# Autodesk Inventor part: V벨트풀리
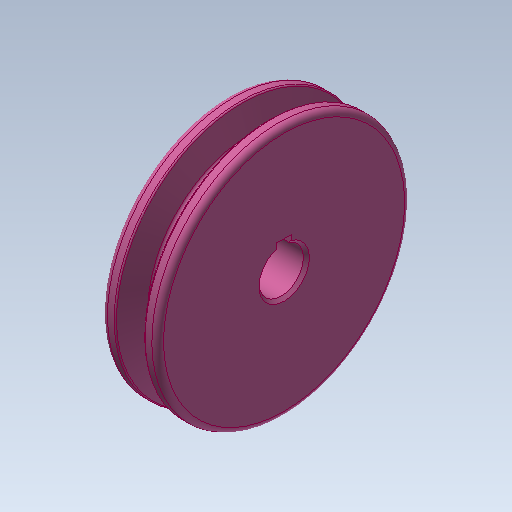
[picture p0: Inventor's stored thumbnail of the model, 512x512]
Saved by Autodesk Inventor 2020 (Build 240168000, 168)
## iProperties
Created: 2018-11
Part Number: V벨트풀리
Material: 알루미늄 6061
Document SubType Name: Modeling
Designer: mduedu
Density: 1 g/cm^3
Appearance: 분홍색
Author: mduedu
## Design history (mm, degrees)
sketch "스케치1"
  geometry: L1 (-9.5, 0)-(9.5, 0); L2 (9.5, 0)-(9.5, 42.7); L3 (9.5, 42.7)-(4.877, 42.7); L4 (-9.5, 42.7)-(-9.5, 0); L5 (-4.877, 42.7)-(-1.953, 33.7); L6 (-1.953, 33.7)-(1.953, 33.7); L7 (1.953, 33.7)-(4.877, 42.7); L8 (0, 0)-(0, 42.7); L9 (-9.5, 40)-(9.5, 40); L10 (-4.877, 42.7)-(-9.5, 42.7); L11 (4.877, 42.7)-(-4.877, 42.7); 3 further points
  constraints: 22 end point, 6 point on line, 4 parallel, 3 perpendicular, 2 midpoint, 1 coincident, 1 horizontal, 1 vertical, 1 other
  dimensions: "d2" = 19 distance of L2.end L4.start; "d3" = 80 diameter of L9 L1; "d4" = 36 deg angle of L7 L5; "d5" = 6.3 distance between parallel lines of L6 L9; "d6" = 8 distance of point (4, 40) point (-4, 40); "d27" = 2.7 distance between parallel lines of L3 L9
revolve "회전1" sketch "스케치1" stored, may be unused: angle "d7" = 90 deg
sketch "스케치2"
  geometry: L1 (-2.5, 7.071)-(2.5, 7.071); L2 (2.5, 7.071)-(2.5, 9.8); L3 (2.5, 9.8)-(-2.5, 9.8); L4 (-2.5, 9.8)-(-2.5, 7.071); A1 r 7.5 centre (0, 0) between (-2.5, 7.071) and (2.5, 7.071); 1 further point
  constraints: 8 end point, 2 parallel, 2 point on circle, 1 centre point, 1 coincident, 1 horizontal, 1 perpendicular
  dimensions: "d8" = 15 diameter of A1; "d10" = 17.3 dimension on A1 L3; "d11" = 5 distance of L2.end L3.end
extrude "돌출1" cut sketch "스케치2" extent not by distance; stored distance "d12" = 10; taper "d13" = 0 deg
chamfer "모따기1" distance "d14" = 1; stored, may be unused: second distance "d15" = 2, angle "d16" = 45 deg
fillet "모깎기1" dims "d17" = 1, "d18" = 0.5, "d19" = 2
sketch "스케치3"
  geometry: C1 r 17.5 at (0, 0); C2 r 28.5 at (0, 0); 1 further point
  constraints: 2 centre point, 2 coincident
  dimensions: "d20" = 35 diameter of C1; "d23" = 57 diameter of C2
extrude "돌출2" cut sketch "스케치3" distance "d24" = 9.5; taper "d25" = 0 deg
fillet "모깎기2" dims "d26" = 3
chamfer "모따기2" distance "d28" = 0.5; stored, may be unused: second distance "d29" = 2, angle "d30" = 45 deg
node "솔리드1"
